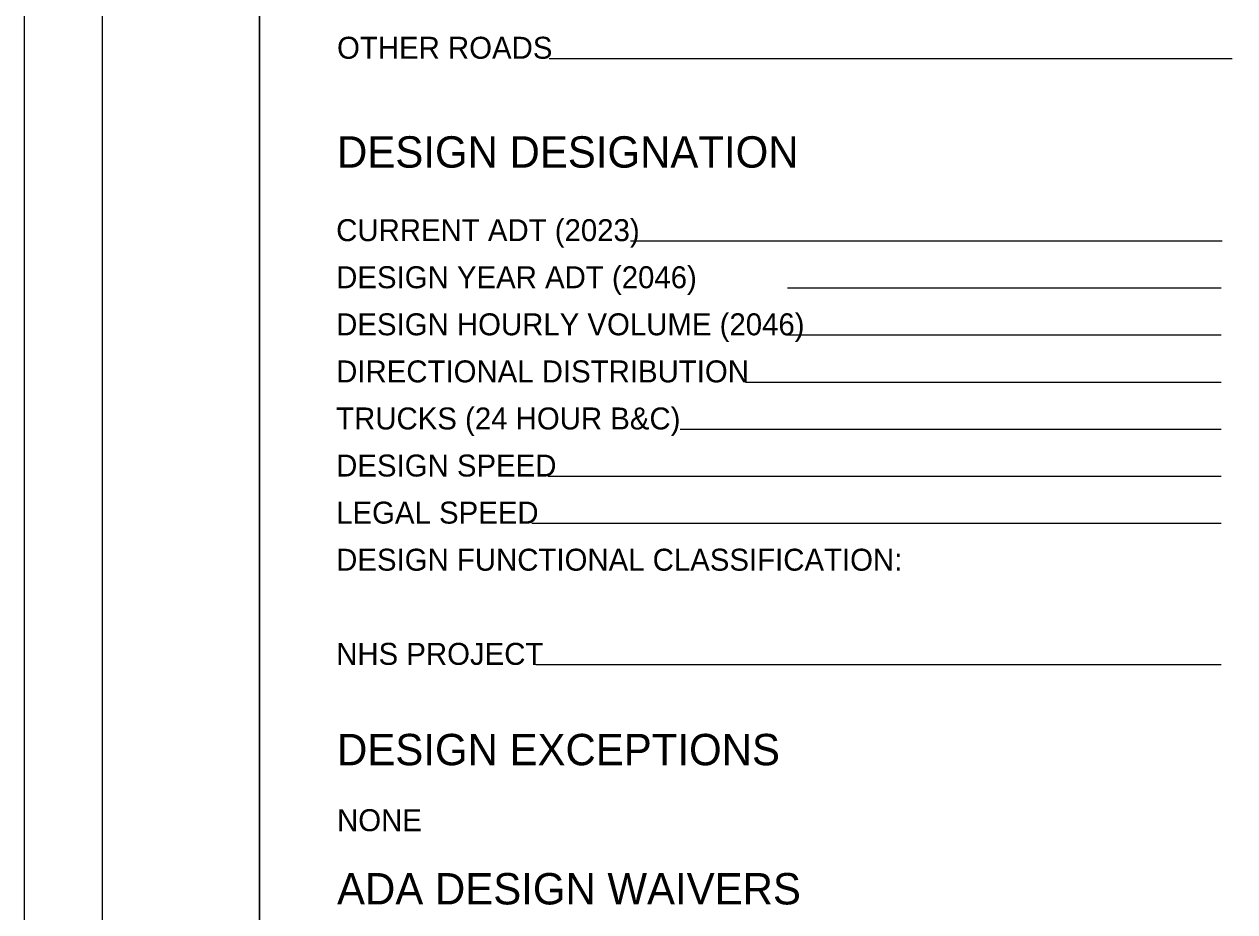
# Model space of a CAD drawing. Extents: x 0 to 34, y 0 to 22.
# Drawn here: x 0 to 7.72, y 5.44 to 11.1 of the extents above; entities that cross this region are included whole.
import ezdxf

# ---------------------------------------------------------------- set-up
doc = ezdxf.new("R2010")
doc.units = 0
for name, color, linetype in [('SH_Border', 7, 'Continuous'), ('SH_Cut_Line', 7, 'Continuous'), ('SH_Data', 7, 'Continuous'), ('SH_Text', 7, 'Continuous')]:
    doc.layers.add(name, color=color, linetype=linetype)

msp = doc.modelspace()

# ---------------------------------------------------------------- linework, layer by layer
at = {"layer": 'SH_Border'}
for points in [[(0.5, 21.5), (1.5, 21.5), (1.5, 0.5), (0.5, 0.5)], [(1.5, 21.5), (33.5, 21.5), (33.5, 0.5), (1.5, 0.5)]]:
    msp.add_lwpolyline(points, close=True, dxfattribs=at)
at = {"layer": 'SH_Cut_Line'}
msp.add_lwpolyline([(0, 0), (34, 0), (34, 22), (0, 22)], close=True, dxfattribs=at)
at = {"layer": 'SH_Data'}
for p, q in [((7.7, 10.8767), (3.3471, 10.8767)), ((7.6368, 9.7143), (3.8654, 9.7143)), ((7.6312, 9.4143), (4.8667, 9.4143)), ((7.6312, 9.1143), (4.8667, 9.1143)), ((7.6312, 8.8143), (4.5981, 8.8143)), ((7.6312, 8.5143), (4.1829, 8.5143)), ((7.6312, 8.2143), (3.3404, 8.2143)), ((7.6312, 7.9143), (3.2366, 7.9143)), ((7.6312, 7.0143), (3.2613, 7.0143))]:
    msp.add_line(p, q, dxfattribs=at)

# ---------------------------------------------------------------- texts
msp.add_text('DESIGN DESIGNATION', height=0.2, dxfattribs=at).set_placement((1.9944, 10.1827))
at = {"layer": 'SH_Text'}
for s, height, p in [('OTHER ROADS', 0.14, (1.9944, 10.8767)), ('CURRENT ADT (2023)', 0.14, (1.9888, 9.7143)), ('DESIGN YEAR ADT (2046)', 0.14, (1.9888, 9.4143)), ('DESIGN HOURLY VOLUME (2046)', 0.14, (1.9888, 9.1143)), ('DIRECTIONAL DISTRIBUTION', 0.14, (1.9888, 8.8143)), ('TRUCKS (24 HOUR B&C)', 0.14, (1.9888, 8.5143)), ('DESIGN SPEED', 0.14, (1.9888, 8.2143)), ('LEGAL SPEED', 0.14, (1.9888, 7.9143)), ('DESIGN FUNCTIONAL CLASSIFICATION:', 0.14, (1.9888, 7.6143)), ('NHS PROJECT', 0.14, (1.9888, 7.0143)), ('DESIGN EXCEPTIONS', 0.2, (1.9944, 6.3744)), ('NONE', 0.14, (1.9944, 5.9544)), ('ADA DESIGN WAIVERS', 0.2, (1.9944, 5.4875))]:
    msp.add_text(s, height=height, dxfattribs=at).set_placement(p)

doc.saveas('drawing.dxf')
